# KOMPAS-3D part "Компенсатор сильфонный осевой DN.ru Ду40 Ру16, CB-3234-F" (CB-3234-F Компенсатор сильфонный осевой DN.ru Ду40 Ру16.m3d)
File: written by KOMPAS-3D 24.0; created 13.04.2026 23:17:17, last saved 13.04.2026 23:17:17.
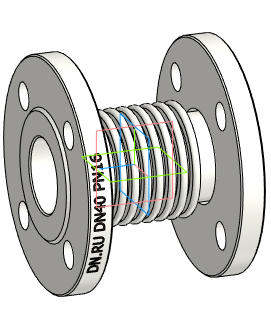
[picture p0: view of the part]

Document properties: Автор: DN.RU; Полное имя файла: D:\PROJECT CAD\DN.RU\...198(ACTUALE). CB-3234-F Компенсатор сильфонный осевой DN.ru\Исходники\DN40\CB-3234-F Компенсатор сильфонный осевой DN.ru Ду40 Ру16.m3d

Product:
- Body: Твердое тело1  | qty 1
    Масса: 4.189436
- Part/product: Компенсатор сильфонный осевой DN.ru Ду40 Ру16  | designation CB-3234-F
    Масса: 3.8
    Раздел спецификации: Прочие изделия
    Комментарий: D140-02112
    Примечание: D140-02112
    additional columns: Типовые

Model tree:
1. Твердое тело1  (labels: Твердое тело1)

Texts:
  CB-3234-F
